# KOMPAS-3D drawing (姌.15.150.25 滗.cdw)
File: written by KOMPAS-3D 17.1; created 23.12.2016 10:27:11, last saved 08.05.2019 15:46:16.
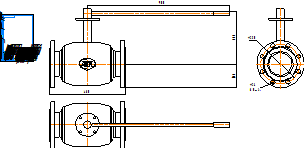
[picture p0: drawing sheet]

Sheet 1: A4, portrait

Title block, sheet 1: name: КШ.15.150.25 фф; material: Внимание! Данный продукт является объектом авторского права ООО «Торговый Дом АДЛ». / Запрещается изменение, копирование, распространение / (в том числе путем копирования на другие сайты и ресурсы в Интернете) / или любое иное использование информации и объектов без предварительного / согласия правообладателя (ООО «Торговый Дом АДЛ»).; sheets: 1; organisation: ООО "Торговый дом АДЛ"; sheet format: A4; stored path: C:\Users\tra\Desktop\2д чертежи\Шаровые краны БИВАЛ\КШ_Бивал_серия_14_15\KOMPAS_2D\КШ.15.150.25 фф.cdw

Views: Вид 1, Проекционный вид 2, Проекционный вид 3
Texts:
  Klimkovich
  ADL
Dimensions and other numbers on the sheet: 480; 900; 336; 150; 250; 26; 8 Отв.; 1:1; 1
